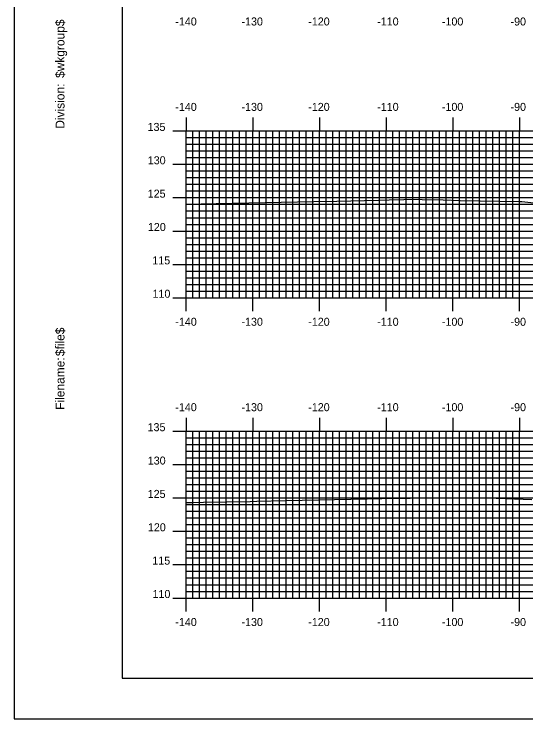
# Model space of a CAD drawing. Extents: x 842962 to 843305, y 363538 to 363758.
# Drawn here: x 842962.1 to 843038.9, y 363537.6 to 363643.2 of the extents above; entities that cross this region are included whole.
import ezdxf

# ---------------------------------------------------------------- set-up
doc = ezdxf.new("R2010")
doc.units = 0
for name, color, linetype in [('BORDER', 7, 'Continuous'), ('H_V ANNOTATION', 7, 'Continuous'), ('M_Roadway_Centerline', 7, 'Continuous'), ('MAJOR', 7, 'Continuous'), ('MINOR', 7, 'Continuous'), ('PLOT BOUNDARY', 7, 'Continuous'), ('S_Roadway_Centerline', 7, 'Continuous')]:
    doc.layers.add(name, color=color, linetype=linetype)

msp = doc.modelspace()

# ---------------------------------------------------------------- linework, layer by layer
at = {"layer": 'BORDER'}
msp.add_lwpolyline([(842978.31, 363543.72), (843298.31, 363543.72), (843298.31, 363753.72), (842978.31, 363753.72)], close=True, dxfattribs=at)
at = {"layer": 'MAJOR'}
for p, q in [((842987.91, 363627.73), (842987.91, 363625.72)), ((842997.91, 363627.73), (842997.91, 363625.72)), ((843007.91, 363627.73), (843007.91, 363625.72)), ((843017.91, 363627.73), (843017.91, 363625.72)), ((843027.91, 363627.73), (843027.91, 363625.72)), ((843037.91, 363627.73), (843037.91, 363625.72)), ((842985.91, 363625.72), (842987.91, 363625.72)), ((842987.91, 363625.72), (843267.91, 363625.72)), ((842987.91, 363600.72), (842987.91, 363625.72)), ((842987.91, 363600.72), (842987.91, 363625.72)), ((842987.91, 363625.72), (843267.91, 363625.72)), ((842997.91, 363600.72), (842997.91, 363625.72)), ((843007.91, 363600.72), (843007.91, 363625.72)), ((843017.91, 363600.72), (843017.91, 363625.72)), ((843027.91, 363600.72), (843027.91, 363625.72)), ((843037.91, 363600.72), (843037.91, 363625.72)), ((842985.91, 363620.72), (842987.91, 363620.72)), ((842987.91, 363620.72), (843267.91, 363620.72)), ((842985.91, 363615.72), (842987.91, 363615.72)), ((842987.91, 363615.72), (843267.91, 363615.72)), ((842985.91, 363610.72), (842987.91, 363610.72)), ((842987.91, 363610.72), (843267.91, 363610.72)), ((842985.91, 363605.72), (842987.91, 363605.72)), ((842987.91, 363605.72), (843267.91, 363605.72)), ((842985.91, 363600.72), (842987.91, 363600.72)), ((842987.91, 363600.72), (843267.91, 363600.72)), ((842987.91, 363600.72), (843267.91, 363600.72)), ((842987.91, 363598.72), (842987.91, 363600.72)), ((842997.91, 363598.72), (842997.91, 363600.72)), ((843007.91, 363598.72), (843007.91, 363600.72)), ((843017.91, 363598.72), (843017.91, 363600.72)), ((843027.91, 363598.72), (843027.91, 363600.72)), ((843037.91, 363598.72), (843037.91, 363600.72)), ((842987.91, 363582.73), (842987.91, 363580.72)), ((842997.91, 363582.73), (842997.91, 363580.72)), ((843007.91, 363582.73), (843007.91, 363580.72)), ((843017.91, 363582.73), (843017.91, 363580.72)), ((843027.91, 363582.73), (843027.91, 363580.72)), ((843037.91, 363582.73), (843037.91, 363580.72)), ((842985.91, 363580.72), (842987.91, 363580.72)), ((842987.91, 363580.72), (843267.91, 363580.72)), ((842987.91, 363555.72), (842987.91, 363580.72)), ((842987.91, 363555.72), (842987.91, 363580.72)), ((842987.91, 363580.72), (843267.91, 363580.72)), ((842997.91, 363555.72), (842997.91, 363580.72)), ((843007.91, 363555.72), (843007.91, 363580.72)), ((843017.91, 363555.72), (843017.91, 363580.72)), ((843027.91, 363555.72), (843027.91, 363580.72)), ((843037.91, 363555.72), (843037.91, 363580.72)), ((842985.91, 363575.72), (842987.91, 363575.72)), ((842987.91, 363575.72), (843267.91, 363575.72)), ((842985.91, 363570.72), (842987.91, 363570.72)), ((842987.91, 363570.72), (843267.91, 363570.72)), ((842985.91, 363565.72), (842987.91, 363565.72)), ((842987.91, 363565.72), (843267.91, 363565.72)), ((842985.91, 363560.72), (842987.91, 363560.72)), ((842987.91, 363560.72), (843267.91, 363560.72)), ((842985.91, 363555.72), (842987.91, 363555.72)), ((842987.91, 363555.72), (843267.91, 363555.72)), ((842987.91, 363555.72), (843267.91, 363555.72)), ((842987.91, 363553.72), (842987.91, 363555.72)), ((842997.91, 363553.72), (842997.91, 363555.72)), ((843007.91, 363553.72), (843007.91, 363555.72)), ((843017.91, 363553.72), (843017.91, 363555.72)), ((843027.91, 363553.72), (843027.91, 363555.72)), ((843037.91, 363553.72), (843037.91, 363555.72))]:
    msp.add_line(p, q, dxfattribs=at)
at = {"layer": 'MINOR'}
for p, q in [((842988.91, 363600.72), (842988.91, 363625.72)), ((842989.91, 363600.72), (842989.91, 363625.72)), ((842990.91, 363600.72), (842990.91, 363625.72)), ((842991.91, 363600.72), (842991.91, 363625.72)), ((842992.91, 363600.72), (842992.91, 363625.72)), ((842993.91, 363600.72), (842993.91, 363625.72)), ((842994.91, 363600.72), (842994.91, 363625.72)), ((842995.91, 363600.72), (842995.91, 363625.72)), ((842996.91, 363600.72), (842996.91, 363625.72)), ((842998.91, 363600.72), (842998.91, 363625.72)), ((842999.91, 363600.72), (842999.91, 363625.72)), ((843000.91, 363600.72), (843000.91, 363625.72)), ((843001.91, 363600.72), (843001.91, 363625.72)), ((843002.91, 363600.72), (843002.91, 363625.72)), ((843003.91, 363600.72), (843003.91, 363625.72)), ((843004.91, 363600.72), (843004.91, 363625.72)), ((843005.91, 363600.72), (843005.91, 363625.72)), ((843006.91, 363600.72), (843006.91, 363625.72)), ((843008.91, 363600.72), (843008.91, 363625.72)), ((843009.91, 363600.72), (843009.91, 363625.72)), ((843010.91, 363600.72), (843010.91, 363625.72)), ((843011.91, 363600.72), (843011.91, 363625.72)), ((843012.91, 363600.72), (843012.91, 363625.72)), ((843013.91, 363600.72), (843013.91, 363625.72)), ((843014.91, 363600.72), (843014.91, 363625.72)), ((843015.91, 363600.72), (843015.91, 363625.72)), ((843016.91, 363600.72), (843016.91, 363625.72)), ((843018.91, 363600.72), (843018.91, 363625.72)), ((843019.91, 363600.72), (843019.91, 363625.72)), ((843020.91, 363600.72), (843020.91, 363625.72)), ((843021.91, 363600.72), (843021.91, 363625.72)), ((843022.91, 363600.72), (843022.91, 363625.72)), ((843023.91, 363600.72), (843023.91, 363625.72)), ((843024.91, 363600.72), (843024.91, 363625.72)), ((843025.91, 363600.72), (843025.91, 363625.72)), ((843026.91, 363600.72), (843026.91, 363625.72)), ((843028.91, 363600.72), (843028.91, 363625.72)), ((843029.91, 363600.72), (843029.91, 363625.72)), ((843030.91, 363600.72), (843030.91, 363625.72)), ((843031.91, 363600.72), (843031.91, 363625.72)), ((843032.91, 363600.72), (843032.91, 363625.72)), ((843033.91, 363600.72), (843033.91, 363625.72)), ((843034.91, 363600.72), (843034.91, 363625.72)), ((843035.91, 363600.72), (843035.91, 363625.72)), ((843036.91, 363600.72), (843036.91, 363625.72)), ((842987.91, 363624.72), (843267.91, 363624.72)), ((842987.91, 363624.72), (842989.92, 363624.72)), ((842987.91, 363623.72), (843267.91, 363623.72)), ((842987.91, 363623.72), (842989.92, 363623.72)), ((842987.91, 363622.72), (843267.91, 363622.72)), ((842987.91, 363622.72), (842989.92, 363622.72)), ((842987.91, 363621.72), (843267.91, 363621.72)), ((842987.91, 363621.72), (842989.92, 363621.72)), ((842987.91, 363619.72), (843267.91, 363619.72)), ((842987.91, 363619.72), (842989.92, 363619.72)), ((842987.91, 363618.72), (843267.91, 363618.72)), ((842987.91, 363618.72), (842989.92, 363618.72)), ((842987.91, 363617.72), (843267.91, 363617.72)), ((842987.91, 363617.72), (842989.92, 363617.72)), ((842987.91, 363616.72), (843267.91, 363616.72)), ((842987.91, 363616.72), (842989.92, 363616.72)), ((842987.91, 363614.72), (843267.91, 363614.72)), ((842987.91, 363614.72), (842989.92, 363614.72)), ((842987.91, 363613.72), (843267.91, 363613.72)), ((842987.91, 363613.72), (842989.92, 363613.72)), ((842987.91, 363612.72), (843267.91, 363612.72)), ((842987.91, 363612.72), (842989.92, 363612.72)), ((842987.91, 363611.72), (843267.91, 363611.72)), ((842987.91, 363611.72), (842989.92, 363611.72)), ((842987.91, 363609.72), (843267.91, 363609.72)), ((842987.91, 363609.72), (842989.92, 363609.72)), ((842987.91, 363608.72), (843267.91, 363608.72)), ((842987.91, 363608.72), (842989.92, 363608.72)), ((842987.91, 363607.72), (843267.91, 363607.72)), ((842987.91, 363607.72), (842989.92, 363607.72)), ((842987.91, 363606.72), (843267.91, 363606.72)), ((842987.91, 363606.72), (842989.92, 363606.72)), ((842987.91, 363604.72), (843267.91, 363604.72)), ((842987.91, 363604.72), (842989.92, 363604.72)), ((842987.91, 363603.72), (843267.91, 363603.72)), ((842987.91, 363603.72), (842989.92, 363603.72)), ((842987.91, 363602.72), (843267.91, 363602.72)), ((842987.91, 363602.72), (842989.92, 363602.72)), ((842987.91, 363601.72), (843267.91, 363601.72)), ((842987.91, 363601.72), (842989.92, 363601.72)), ((842988.91, 363555.72), (842988.91, 363580.72)), ((842989.91, 363555.72), (842989.91, 363580.72)), ((842990.91, 363555.72), (842990.91, 363580.72)), ((842991.91, 363555.72), (842991.91, 363580.72)), ((842992.91, 363555.72), (842992.91, 363580.72)), ((842993.91, 363555.72), (842993.91, 363580.72)), ((842994.91, 363555.72), (842994.91, 363580.72)), ((842995.91, 363555.72), (842995.91, 363580.72)), ((842996.91, 363555.72), (842996.91, 363580.72)), ((842998.91, 363555.72), (842998.91, 363580.72)), ((842999.91, 363555.72), (842999.91, 363580.72)), ((843000.91, 363555.72), (843000.91, 363580.72)), ((843001.91, 363555.72), (843001.91, 363580.72)), ((843002.91, 363555.72), (843002.91, 363580.72)), ((843003.91, 363555.72), (843003.91, 363580.72)), ((843004.91, 363555.72), (843004.91, 363580.72)), ((843005.91, 363555.72), (843005.91, 363580.72)), ((843006.91, 363555.72), (843006.91, 363580.72)), ((843008.91, 363555.72), (843008.91, 363580.72)), ((843009.91, 363555.72), (843009.91, 363580.72)), ((843010.91, 363555.72), (843010.91, 363580.72)), ((843011.91, 363555.72), (843011.91, 363580.72)), ((843012.91, 363555.72), (843012.91, 363580.72)), ((843013.91, 363555.72), (843013.91, 363580.72)), ((843014.91, 363555.72), (843014.91, 363580.72)), ((843015.91, 363555.72), (843015.91, 363580.72)), ((843016.91, 363555.72), (843016.91, 363580.72)), ((843018.91, 363555.72), (843018.91, 363580.72)), ((843019.91, 363555.72), (843019.91, 363580.72)), ((843020.91, 363555.72), (843020.91, 363580.72)), ((843021.91, 363555.72), (843021.91, 363580.72)), ((843022.91, 363555.72), (843022.91, 363580.72)), ((843023.91, 363555.72), (843023.91, 363580.72)), ((843024.91, 363555.72), (843024.91, 363580.72)), ((843025.91, 363555.72), (843025.91, 363580.72)), ((843026.91, 363555.72), (843026.91, 363580.72)), ((843028.91, 363555.72), (843028.91, 363580.72)), ((843029.91, 363555.72), (843029.91, 363580.72)), ((843030.91, 363555.72), (843030.91, 363580.72)), ((843031.91, 363555.72), (843031.91, 363580.72)), ((843032.91, 363555.72), (843032.91, 363580.72)), ((843033.91, 363555.72), (843033.91, 363580.72)), ((843034.91, 363555.72), (843034.91, 363580.72)), ((843035.91, 363555.72), (843035.91, 363580.72)), ((843036.91, 363555.72), (843036.91, 363580.72)), ((842987.91, 363579.72), (843267.91, 363579.72)), ((842987.91, 363579.72), (842989.92, 363579.72)), ((842987.91, 363578.72), (843267.91, 363578.72)), ((842987.91, 363578.72), (842989.92, 363578.72)), ((842987.91, 363577.72), (843267.91, 363577.72)), ((842987.91, 363577.72), (842989.92, 363577.72)), ((842987.91, 363576.72), (843267.91, 363576.72)), ((842987.91, 363576.72), (842989.92, 363576.72)), ((842987.91, 363574.72), (843267.91, 363574.72)), ((842987.91, 363574.72), (842989.92, 363574.72)), ((842987.91, 363573.72), (843267.91, 363573.72)), ((842987.91, 363573.72), (842989.92, 363573.72)), ((842987.91, 363572.72), (843267.91, 363572.72)), ((842987.91, 363572.72), (842989.92, 363572.72)), ((842987.91, 363571.72), (843267.91, 363571.72)), ((842987.91, 363571.72), (842989.92, 363571.72)), ((842987.91, 363569.72), (843267.91, 363569.72)), ((842987.91, 363569.72), (842989.92, 363569.72)), ((842987.91, 363568.72), (843267.91, 363568.72)), ((842987.91, 363568.72), (842989.92, 363568.72)), ((842987.91, 363567.72), (843267.91, 363567.72)), ((842987.91, 363567.72), (842989.92, 363567.72)), ((842987.91, 363566.72), (843267.91, 363566.72)), ((842987.91, 363566.72), (842989.92, 363566.72)), ((842987.91, 363564.72), (843267.91, 363564.72)), ((842987.91, 363564.72), (842989.92, 363564.72)), ((842987.91, 363563.72), (843267.91, 363563.72)), ((842987.91, 363563.72), (842989.92, 363563.72)), ((842987.91, 363562.72), (843267.91, 363562.72)), ((842987.91, 363562.72), (842989.92, 363562.72)), ((842987.91, 363561.72), (843267.91, 363561.72)), ((842987.91, 363561.72), (842989.92, 363561.72)), ((842987.91, 363559.72), (843267.91, 363559.72)), ((842987.91, 363559.72), (842989.92, 363559.72)), ((842987.91, 363558.72), (843267.91, 363558.72)), ((842987.91, 363558.72), (842989.92, 363558.72)), ((842987.91, 363557.72), (843267.91, 363557.72)), ((842987.91, 363557.72), (842989.92, 363557.72)), ((842987.91, 363556.72), (843267.91, 363556.72)), ((842987.91, 363556.72), (842989.92, 363556.72))]:
    msp.add_line(p, q, dxfattribs=at)
at = {"layer": 'PLOT BOUNDARY'}
msp.add_lwpolyline([(842962.12, 363537.6), (843302.12, 363537.6), (843302.12, 363757.6), (842962.12, 363757.6)], close=True, dxfattribs=at)
at = {"layer": 'S_Roadway_Centerline'}
for points in [[(842987.91, 363614.73), (842992.41, 363614.82), (843007.05, 363615.13), (843010.54, 363615.21), (843016.75, 363615.36), (843018.35, 363615.38), (843022.75, 363615.47), (843023.29, 363615.43), (843026.44, 363615.39), (843028.99, 363615.31), (843037.96, 363615.12), (843038.27, 363615.12), (843045.97, 363614.27)], [(842987.91, 363570.02), (842988.8, 363570.04), (842988.94, 363570.04), (842990.5, 363570.08), (842997.53, 363570.2), (842998.52, 363570.22), (843002.86, 363570.31), (843015.06, 363570.56), (843019.52, 363570.66), (843021.52, 363570.7), (843023.51, 363570.72), (843024.17, 363570.74), (843024.67, 363570.75), (843034.43, 363570.66), (843034.51, 363570.66), (843039.76, 363570.47)]]:
    msp.add_lwpolyline(points, dxfattribs=at)

# ---------------------------------------------------------------- texts
at = {"layer": 'BORDER'}
for s, p in [('$wkgroup$', (842969.68, 363633.66)), ('Division:', (842969.68, 363626.05)), ('$file$', (842969.68, 363591.97)), ('Filename:', (842969.68, 363583.92))]:
    msp.add_text(s, height=1.339, rotation=90, dxfattribs=at).set_placement(p)
at = {"layer": 'H_V ANNOTATION'}
for s, p in [('-140', (842986.3, 363641.52)), ('-130', (842996.22, 363641.52)), ('-120', (843006.23, 363641.52)), ('-110', (843016.57, 363641.52)), ('-100', (843026.27, 363641.52)), ('-90', (843036.56, 363641.52)), ('-140', (842986.3, 363628.72)), ('-130', (842996.22, 363628.72)), ('-120', (843006.23, 363628.72)), ('-110', (843016.57, 363628.72)), ('-100', (843026.27, 363628.72)), ('-90', (843036.56, 363628.72)), ('135', (842982.14, 363625.72)), ('130', (842982.17, 363620.72)), ('125', (842982.16, 363615.72)), ('120', (842982.19, 363610.72)), ('115', (842982.85, 363605.72)), ('110', (842982.88, 363600.72)), ('-140', (842986.3, 363596.52)), ('-130', (842996.22, 363596.52)), ('-120', (843006.23, 363596.52)), ('-110', (843016.57, 363596.52)), ('-100', (843026.27, 363596.52)), ('-90', (843036.56, 363596.52)), ('-140', (842986.3, 363583.72)), ('-130', (842996.22, 363583.72)), ('-120', (843006.23, 363583.72)), ('-110', (843016.57, 363583.72)), ('-100', (843026.27, 363583.72)), ('-90', (843036.56, 363583.72)), ('135', (842982.14, 363580.72)), ('130', (842982.17, 363575.72)), ('125', (842982.16, 363570.72)), ('120', (842982.19, 363565.72)), ('115', (842982.85, 363560.72)), ('110', (842982.88, 363555.72)), ('-140', (842986.3, 363551.52)), ('-130', (842996.22, 363551.52)), ('-120', (843006.23, 363551.52)), ('-110', (843016.57, 363551.52)), ('-100', (843026.27, 363551.52)), ('-90', (843036.56, 363551.52))]:
    msp.add_text(s, height=1.2, dxfattribs=at).set_placement(p)
at = {"layer": 'M_Roadway_Centerline'}
for s, p in [('C', (843022.74, 363615.47)), ('L', (843022.75, 363615.46)), ('C', (843024.17, 363570.74)), ('L', (843024.17, 363570.73)), ('C', (842988.94, 363570.04)), ('L', (842988.94, 363570.03))]:
    msp.add_text(s, height=0.0146, dxfattribs=at).set_placement(p)
at = {"layer": 'MAJOR'}
for p in [(842987.9, 363600.72), (842987.9, 363555.72)]:
    msp.add_text('-', height=0.012, dxfattribs=at).set_placement(p)

doc.saveas('drawing.dxf')
